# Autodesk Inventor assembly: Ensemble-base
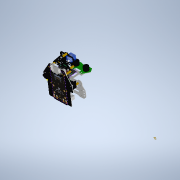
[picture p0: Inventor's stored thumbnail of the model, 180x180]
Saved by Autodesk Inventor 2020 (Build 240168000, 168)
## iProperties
Created: 2021-10
Part Number: Ensemble-base
Document SubType Name: Assembly
Designer: bruno
Mass: 78.0707 g
Surface Area: 663.807 cm^2
Volume: 70.3901 cm^3
Density: 1.10912 g/cm^3
Author: bruno
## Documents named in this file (11)
- C:\Users\bruno\OneDrive\Bureau\Robot-Inventor\Robot-Maqueen\Ensemble-base.iam
- C:\Users\bruno\OneDrive\Bureau\Robot-Inventor\Robot-Maqueen\base.ipt
- C:\Users\bruno\OneDrive\Bureau\Robot-Inventor\Robot-Maqueen\support-roue.ipt
- C:\Users\bruno\OneDrive\Bureau\Robot-Inventor\Robot-Maqueen\ecrou-hexa-2.ipt
- C:\Users\bruno\Documents\Inventor\Content Center Files\R2020\fr-FR\ANSI B18.6.7M(01)\ANSI B18.6.7M - M3x0,5 x 5(5).ipt
- C:\Users\bruno\OneDrive\Bureau\Robot-Inventor\Robot-Maqueen\pile.ipt
- C:\Users\bruno\OneDrive\Bureau\Robot-Inventor\Robot-Maqueen\microbit.ipt
- C:\Users\bruno\OneDrive\Bureau\Robot-Inventor\Robot-Maqueen\Ensemble-final.iam
- C:\Users\bruno\OneDrive\Bureau\Robot-Inventor\Robot-Maqueen\support-capteur.ipt
- C:\Users\bruno\OneDrive\Bureau\Robot-Inventor\Robot-Maqueen\capteur-ultrasons.ipt
- C:\Users\bruno\OneDrive\Bureau\Robot-Inventor\Robot-Maqueen\ecrou-hexa-3.ipt
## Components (14 placed, 10 different names)
1. base:1 — Placage:1, Placage:2, Placage:3, Placage:4, Placage:5, Placage:6, Placage:13, Placage:14, Placage:17, Placage:18, Placage:19, Affleurement:1, Logement:2, Logement:3, Logement:4
2. support-roue:1 — Placage:1, Placage:2, Affleurement:1
3. ecrou-hexa-2:1 — Placage:3, Placage:6, Placage:11, Placage:20, Tangente:2
4. ecrou-hexa-2:2 — Placage:4, Placage:5, Placage:9, Tangente:1
5. Vis à tête tronconique à empreinte cruciforme - Type IA - Métrique M3x0,5 x 5:1 — Placage:9, Placage:22
6. Vis à tête tronconique à empreinte cruciforme - Type IA - Métrique M3x0,5 x 5:2 — Placage:11, Placage:21
7. pile:1 — Placage:13, Placage:14
8. microbit:1 — Placage:17, Placage:18, Placage:19
9. Ensemble-final:1 [sub-assembly] — Placage:20, Tangente:1, Tangente:2, Placage:21, Placage:22
10. support-capteur:1 — Logement:1, Placage:23, Logement:5, Logement:6
11. capteur-ultrasons:1 — Logement:1, Placage:23
12. ecrou-hexa-3:1 — Logement:2
13. ecrou-hexa-3:2 — Logement:3, Logement:6
14. ecrou-hexa-3:3 — Logement:4, Logement:5
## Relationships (26: Mate 17, Insert 6, Tangent 2, Flush 1)
- Placage:1 [Mate]: base:1 ↔ support-roue:1
- Placage:2 [Mate]: base:1 ↔ support-roue:1
- Placage:3 [Mate]: base:1 ↔ ecrou-hexa-2:1
- Placage:4 [Mate]: base:1 ↔ ecrou-hexa-2:2
- Placage:5 [Mate]: base:1 ↔ ecrou-hexa-2:2
- Placage:6 [Mate]: base:1 ↔ ecrou-hexa-2:1
- Placage:9 [Mate]: ecrou-hexa-2:2 ↔ Vis à tête tronconique à empreinte cruciforme - Type IA - Métrique M3x0,5 x 5:1
- Placage:11 [Mate]: ecrou-hexa-2:1 ↔ Vis à tête tronconique à empreinte cruciforme - Type IA - Métrique M3x0,5 x 5:2
- Placage:13 [Mate]: base:1 ↔ pile:1
- Placage:14 [Mate]: base:1 ↔ pile:1
- Placage:17 [Mate]: base:1 ↔ microbit:1
- Placage:18 [Mate]: base:1 ↔ microbit:1
- Placage:19 [Mate]: base:1 ↔ microbit:1
- Affleurement:1 [Flush]: base:1 ↔ support-roue:1
- Placage:20 [Mate]: ecrou-hexa-2:1 ↔ Ensemble-final:1
- Tangente:1: ecrou-hexa-2:2 ↔ Ensemble-final:1
- Tangente:2: ecrou-hexa-2:1 ↔ Ensemble-final:1
- Placage:21 [Mate]: Vis à tête tronconique à empreinte cruciforme - Type IA - Métrique M3x0,5 x 5:2 ↔ Ensemble-final:1
- Placage:22 [Mate]: Vis à tête tronconique à empreinte cruciforme - Type IA - Métrique M3x0,5 x 5:1 ↔ Ensemble-final:1
- Logement:1 [Insert]: support-capteur:1 ↔ capteur-ultrasons:1
- Placage:23 [Mate]: support-capteur:1 ↔ capteur-ultrasons:1
- Logement:2 [Insert]: base:1 ↔ ecrou-hexa-3:1
- Logement:3 [Insert]: base:1 ↔ ecrou-hexa-3:2
- Logement:4 [Insert]: base:1 ↔ ecrou-hexa-3:3
- Logement:5 [Insert]: support-capteur:1 ↔ ecrou-hexa-3:3
- Logement:6 [Insert]: support-capteur:1 ↔ ecrou-hexa-3:2
